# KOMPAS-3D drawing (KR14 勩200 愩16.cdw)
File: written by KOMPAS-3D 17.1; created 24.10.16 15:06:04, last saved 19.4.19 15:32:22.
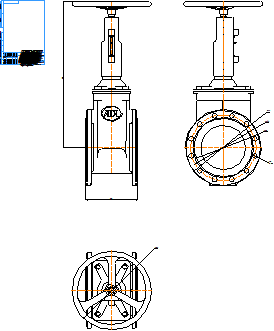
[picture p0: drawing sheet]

Sheet 1: A4, portrait

Title block, sheet 1: name: KR14 Ду200 Ру16; material: Внимание! Данный продукт является объектом авторского права ООО «Торговый Дом АДЛ». / Запрещается изменение, копирование, распространение / (в том числе путем копирования на другие сайты и ресурсы в Интернете) / или любое иное использование информации и объектов без предварительного / согласия правообладателя (ООО «Торговый Дом АДЛ»).; mass: 71; sheets: 1; organisation: ООО "Торговый дом АДЛ"; sheet format: A4; stored path: \\adlc.lan\data\АДЛ_ПКД\3D-модели\ADL production\Клиновые задвижки серии KR ГРАНАР\Клиновые задвижки KR14\kompas 2d\KR14 Ду200 Ру16.cdw

Views: Вид 1
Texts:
  Klimkovich
  ADL
Dimensions and other numbers on the sheet: 230; 653; 1:1; 1; 71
